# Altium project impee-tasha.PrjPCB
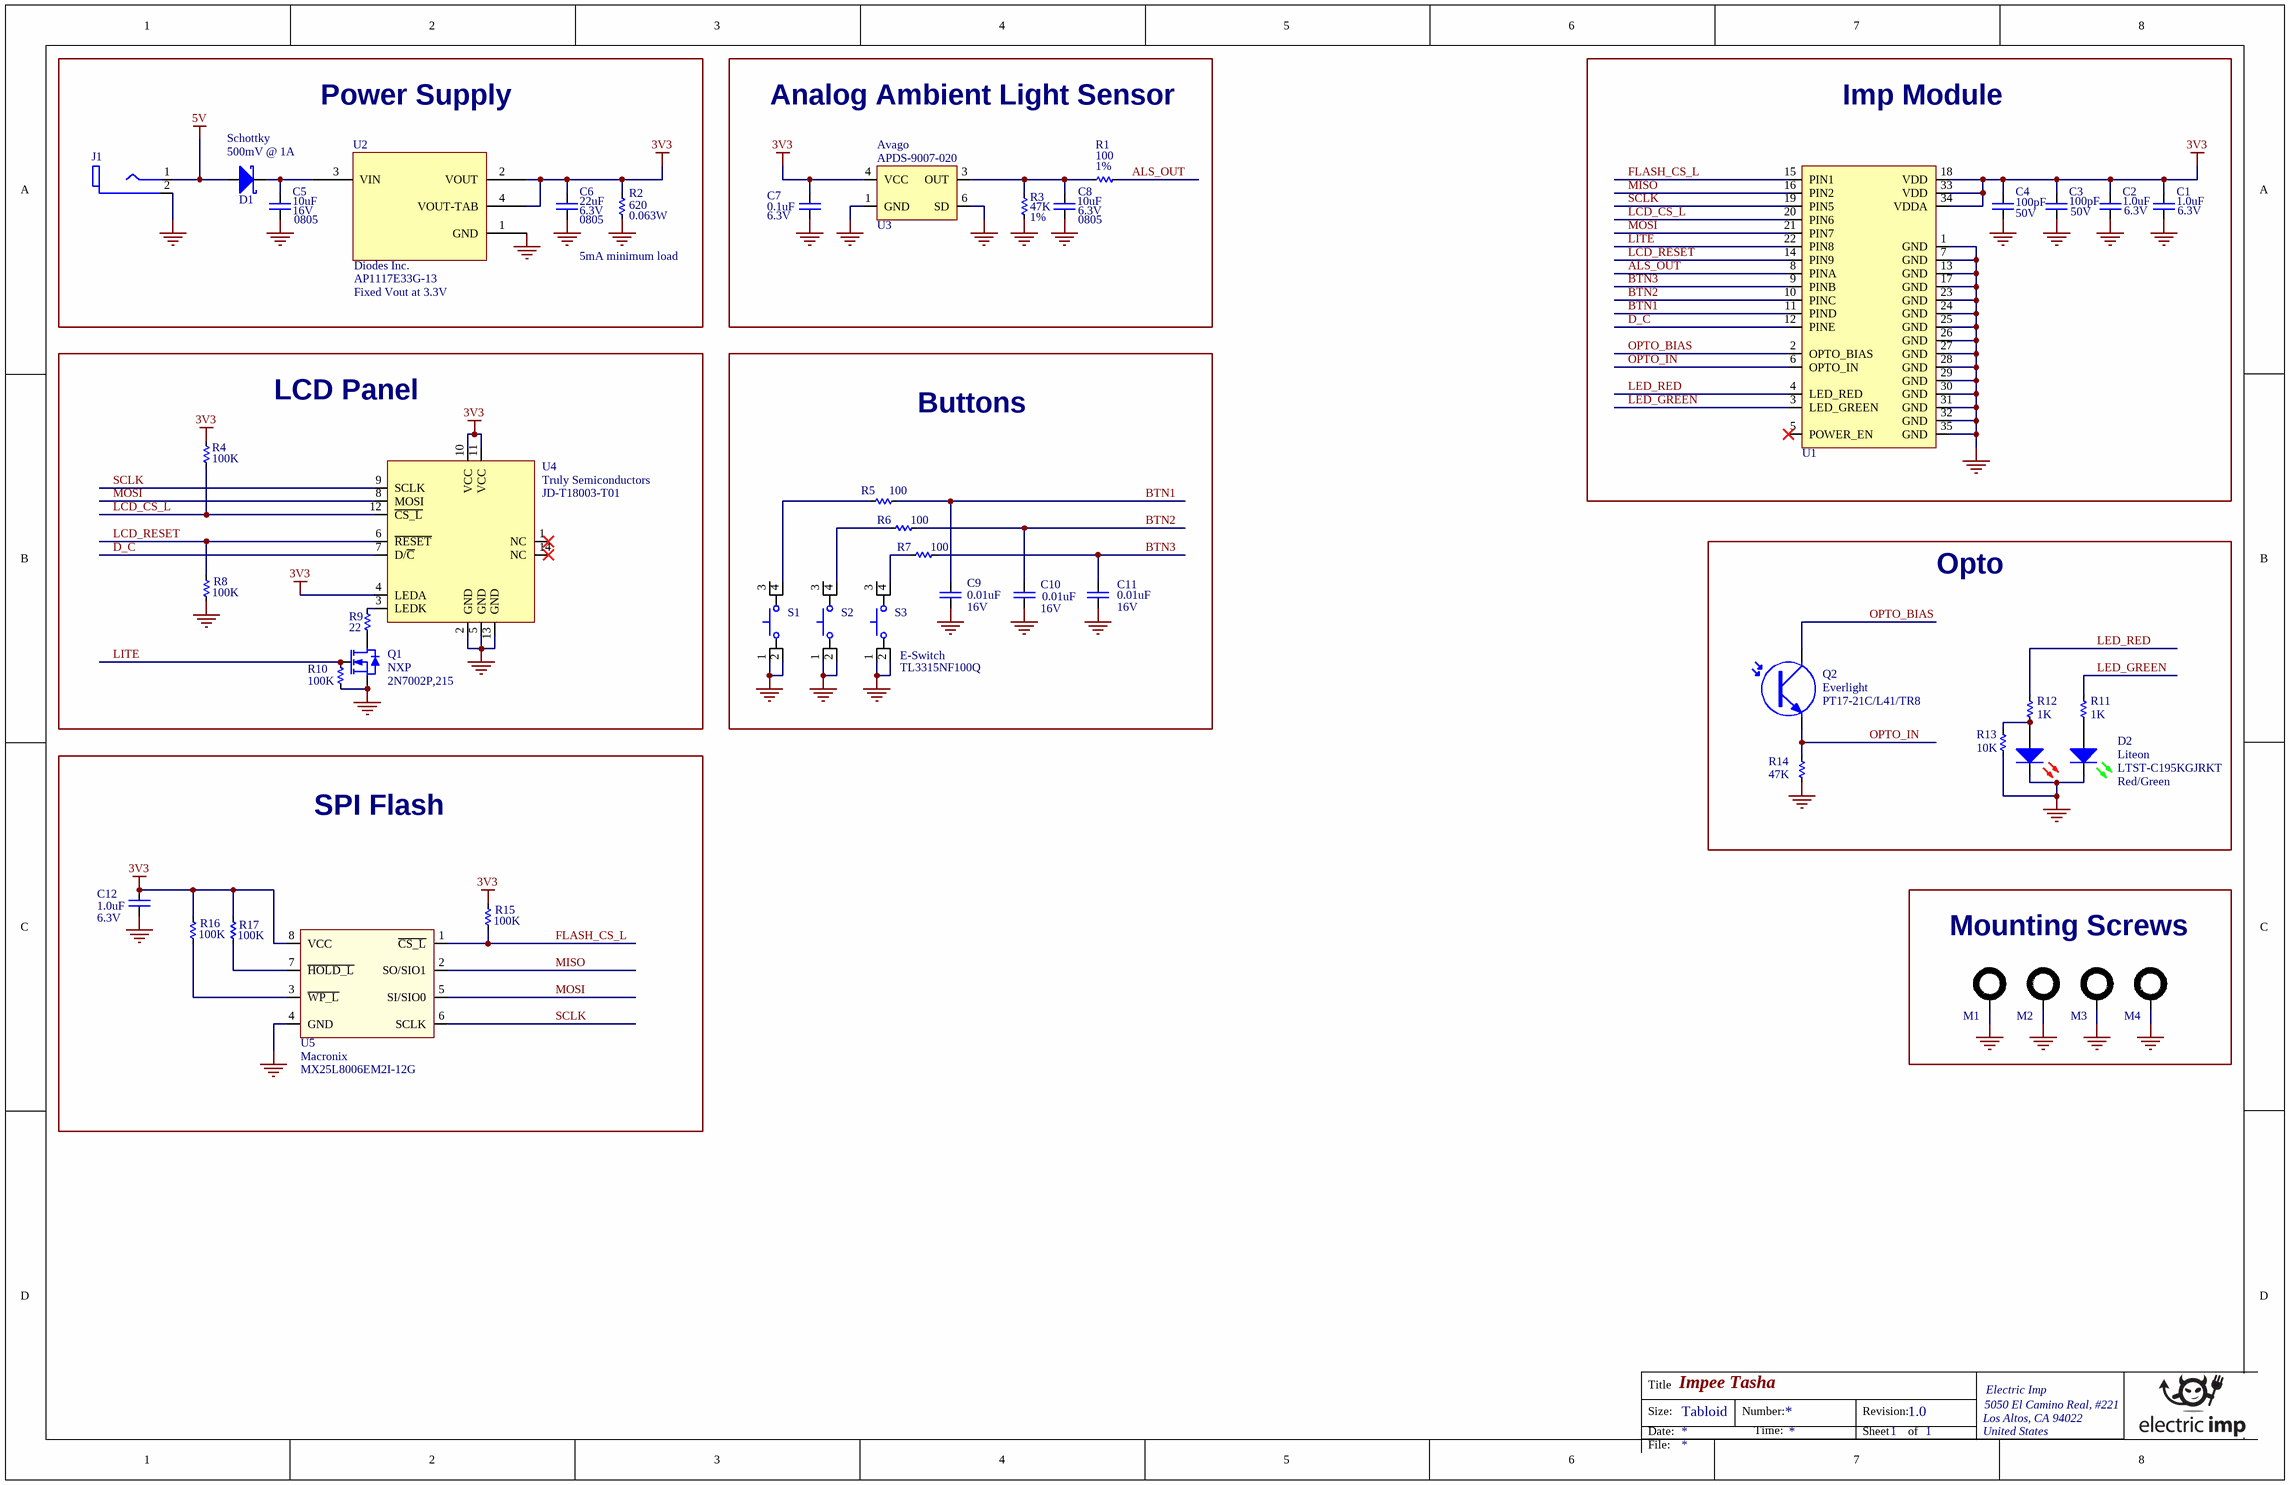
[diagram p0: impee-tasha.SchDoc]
1 sheet, 46 parts. Net scope: global (net labels, ports and power ports of the same name join across sheets).
Board file: impee-tasha.PcbDoc

## Sheet impee-tasha.SchDoc: Impee Tasha
size Tabloid; Address1: Electric Imp; Address2: 5050 El Camino Real, #221; Address3: Los Altos, CA 94022; Address4: United States; Revision: 1.0; SheetNumber: 1; SheetTotal: 1; PageSetup: Record=PageOptions¦CenterHorizontal=True¦CenterVertical=True¦PrintScale=0.98¦XCorrection=1.00¦YCorrection=1.00¦PrintKind=0¦BorderSize=5000000¦LeftOffset=0¦BottomOffset=0¦Orientation=2¦PaperLength=1000¦PaperWidth=1000¦Scale=100¦PaperSource=7¦PrintQuality=600¦MediaType=1¦DitherType=10¦PaperKind=Tabloid¦PrintScaleMode=1

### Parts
C1  value 1.0uF  Voltage: 6.3V  [CAPC1005X07N]  (hidden comment: Ceramic Capacitor)
C2  value 1.0uF  Voltage: 6.3V  [CAPC1005X07N]  (hidden comment: Ceramic Capacitor)
C3  value 100pF  Voltage: 50V  [CAPC1005X07N]  (hidden comment: Ceramic Capacitor)
C4  value 100pF  Voltage: 50V  [CAPC1005X07N]  (hidden comment: Ceramic Capacitor)
C5  value 10uF  Voltage: 16V  Package: 0805  [CAPC2012X14N]  (hidden comment: Ceramic Capacitor)
C6  value 22uF  Voltage: 6.3V  Package: 0805  [CAPC2012X14N]  (hidden comment: Ceramic Capacitor)
C7  value 0.1uF  Voltage: 6.3V  [CAPC1005X07N]  (hidden comment: Ceramic Capacitor)
C8  value 10uF  Voltage: 6.3V  Package: 0805  [CAPC2012X14N]  (hidden comment: Ceramic Capacitor)
C9  value 0.01uF  Voltage: 16V  [CAPC1005X07N]  (hidden comment: Ceramic Capacitor)
C10  value 0.01uF  Voltage: 16V  [CAPC1005X07N]  (hidden comment: Ceramic Capacitor)
C11  value 0.01uF  Voltage: 16V  [CAPC1005X07N]  (hidden comment: Ceramic Capacitor)
C12  value 1.0uF  Voltage: 6.3V  [CAPC1005X07N]  (hidden comment: Ceramic Capacitor)
D1  Voltage - Forward (Vf) (Max) @ If: 500mV @ 1A  [DO-214AC]  (hidden comment: Schottky Diode)
D2  Color: Red/Green  Manufacturer: Liteon  Manufacturer Part Number: LTST-C195KGJRKT  [LED1616X07N-REDGREEN]  (hidden comment: LED Red and Green)
J1  PWR2.1  [HDR1X2]  (value not drawn)
M1  Mounting Hole  [91772A074]  (value not drawn)  (no BOM)
M2  Mounting Hole  [91772A074]  (value not drawn)  (no BOM)
M3  Mounting Hole  [91772A074]  (value not drawn)  (no BOM)
M4  Mounting Hole  [91772A074]  (value not drawn)  (no BOM)
Q1  Manufacturer: NXP  Manufacturer Part Number: 2N7002P,215  [SOT95P300X130-3N]  (hidden comment: N-Channel MOSFET)
Q2  Manufacturer: Everlight  Manufacturer Part Number: PT17-21C/L41/TR8  [PHOTOTRANS2012X13]  (hidden comment: PHOTOTRANSISTOR)
R1  value 100  Tolerance: 1%  [RESC1005X04N]  (hidden comment: Resistor)
R2  value 620  Power: 0.063W  [RESC1005X04N]  (hidden comment: Resistor)
R3  value 47K  Tolerance: 1%  [RESC1005X04N]  (hidden comment: Resistor)
R4  value 100K  [RESC1005X04N]  (hidden comment: Resistor)
R5  value 100  [RESC1005X04N]  (hidden comment: Resistor)
R6  value 100  [RESC1005X04N]  (hidden comment: Resistor)
R7  value 100  [RESC1005X04N]  (hidden comment: Resistor)
R8  value 100K  [RESC1005X04N]  (hidden comment: Resistor)
R9  value 22  [RESC1005X04N]  (hidden comment: Resistor)
R10  value 100K  [RESC1005X04N]  (hidden comment: Resistor)
R11  value 1K  [RESC1005X04N]  (hidden comment: Resistor)
R12  value 1K  [RESC1005X04N]  (hidden comment: Resistor)
R13  value 10K  [RESC1005X04N]  (hidden comment: Resistor)
R14  value 47K  [RESC1005X04N]  (hidden comment: Resistor)
R15  value 100K  [RESC1005X04N]  (hidden comment: Resistor)
R16  value 100K  [RESC1005X04N]  (hidden comment: Resistor)
R17  value 100K  [RESC1005X04N]  (hidden comment: Resistor)
S1  Manufacturer: E-Switch  [TL3315NF100Q]  (hidden comment: Push Button)
S2  Push Button  [TL3315NF100Q]  (value not drawn)
S3  Push Button  [TL3315NF100Q]  (value not drawn)
U1  imp module  [IMP_MODULE]  (value not drawn)
U2  Manufacturer: Diodes Inc.  Manufacturer Part Number: AP1117E33G-13  Comment_1: Fixed Vout at 3.3V  [SOT230P700X180-4N]  (hidden comment: AP1117E33G)
U3  Manufacturer: Avago  Manufacturer Part Number: APDS-9007-020  [APDS-9007]  (hidden comment: APDS-9007)
U4  Manufacturer: Truly Semiconductors  [JD-T18003-T01]  (hidden comment: JD-T18003-T01)
U5  Manufacturer: Macronix  [SOIC127P790X216-8N]  (hidden comment: MX25L8006EM2I-12G)

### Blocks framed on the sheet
Power Supply: C5 C6 D1 J1 R2 U2
Analog Ambient Light Sensor: C7 C8 R1 R3 U3
Imp Module: C1-C4 U1
LCD Panel: Q1 R4 R8-R10 U4
Buttons: C9-C11 R5-R7 S1-S3
Opto: D2 Q2 R11-R14
SPI Flash: C12 R15-R17 U5
Mounting Screws: M1-M4

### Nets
3V3: C1.2 C2.2 C3.2 C4.2 C6.2 C7.2 C12.2 R2.2 R4.2 R15.2 R16.2 R17.2 U1.18(VDD) U1.33(VDD) U1.34(VDDA) U2.2(VOUT) U2.4(VOUT-TAB) U3.4(VCC) U4.4(LEDA) U4.10(VCC) U4.11(VCC) U5.8(VCC)
5V: D1.A J1.1
GND: C1.1 C2.1 C3.1 C4.1 C5.1 C6.1 C7.1 C8.1 C9.1 C10.1 C11.1 C12.1 D2.KG D2.KR J1.2 M1.1 M2.1 M3.1 M4.1 Q1.2(S) R2.1 R3.1 R8.1 R10.1 R13.2 R14.1 S1.1 S1.2 S2.1 S2.2 S3.1 S3.2 U1.1(GND) U1.7(GND) U1.13(GND) U1.17(GND) U1.23(GND) U1.24(GND) U1.25(GND) U1.26(GND) U1.27(GND) U1.28(GND) U1.29(GND) U1.30(GND) U1.31(GND) U1.32(GND) U1.35(GND) U2.1(GND) U3.1(GND) U3.6(SD) U4.2(GND) U4.5(GND) U4.13(GND) U5.4(GND)
ALS_OUT: R1.2 U1.8(PINA)
BTN1: C9.2 R5.1 U1.11(PIND)
BTN2: C10.2 R6.1 U1.10(PINC)
BTN3: C11.2 R7.1 U1.9(PINB)
D_C: U1.12(PINE) U4.7(D/~{C})
FLASH_CS_L: R15.1 U1.15(PIN1) U5.1(~{CS_L})
LCD_CS_L: R4.1 U1.20(PIN6) U4.12(~{CS_L})
LCD_RESET: R8.2 U1.14(PIN9) U4.6(~{RESET})
LED_GREEN: R11.2 U1.3(LED_GREEN)
LED_RED: R12.2 U1.4(LED_RED)
LITE: Q1.1(G) R10.2 U1.22(PIN8)
MISO: U1.16(PIN2) U5.2(SO/SIO1)
MOSI: U1.21(PIN7) U4.8(MOSI) U5.5(SI/SIO0)
OPTO_BIAS: Q2.C U1.2(OPTO_BIAS)
OPTO_IN: Q2.E R14.2 U1.6(OPTO_IN)
SCLK: U1.19(PIN5) U4.9(SCLK) U5.6(SCLK)
NetC5_2: C5.2 D1.K U2.3(VIN)
NetC8_2: C8.2 R1.1 R3.2 U3.3(OUT)
NetD2_AG: D2.AG R11.1
NetD2_AR: D2.AR R12.1 R13.1
NetQ1_3: Q1.3(D) R9.1
NetR5_2: R5.2 S1.4
NetR6_2: R6.2 S2.4
NetR7_2: R7.2 S3.4
NetR9_2: R9.2 U4.3(LEDK)
NetR16_1: R16.1 U5.3(~{WP_L})
NetR17_1: R17.1 U5.7(~{HOLD_L})

Not connected (* = marked no-connect by the designer): S1 3; S2 3; S3 3; U1 5(POWER_EN)*; U4 1(NC)* 14(NC)*

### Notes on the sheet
- 5mA minimum load

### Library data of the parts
C1 C2 C12 = CAPC00005: CAP,X5R,1.0uF,10%,6.3V, 0402,#; Manufacturer: Taiyo Yuden; Manufacturer Part Number: JMK105BJ105KV-F
C3 C4 = CAPC00043: CAP,C0G,100pF,5%,50V,0402; Manufacturer: Yageo; Manufacturer Part Number: CC0402JRNPO9BN101
C5 = CAPC00037: CAP,X5R,10uF,10%,16V,0805,#; Manufacturer: Taiyo Yuden; Manufacturer Part Number: EMK212BJ106KG-T
C6 = CAPC00039: CAP,X5R,22uF,10%,6.3V,0805,#; Manufacturer: TDK; Manufacturer Part Number: C2012X5R0J226K/1.25
C7 = CAPC00002: CAP,X5R,0.1uF,10%,6.3V, 0402,#; Manufacturer: TDK; Manufacturer Part Number: C1005X5R0J104K
C8 = CAPC00036: CAP,X5R,10uF,10%,6.3V,0805,#; Manufacturer: Yageo; Manufacturer Part Number: CC0805KKX5R5BB106
C9-C11 = CAPC00026: CAP,X7R,0.01uF,10%,16V,0402,#; Manufacturer: Yageo; Manufacturer Part Number: CC0402KRX7R7BB103
D1 = SCHOTTKY00001: DIODE, Schottky, 1A, 20V, DO-214AC; Manufacturer: Comchip Technology; Manufacturer Part Number: CDBA120-G
D2 = LED00012: LED, Red and Green, 2/2V, 631/571nm, 15/20mcd, SMT; Millicandela Rating (min): 15mcd, 20mcd; Voltage - Forward (Vf) Typ: 2V, 2V; Current - Test: 20mA; Wavelength - Dominant: 631nm, 571nm; Wavelength - Peak: 639nm, 574nm; Viewing Angle: 130°; Lens Type: Clear
J1 = CON00007: DC Power Jack, 2.1mm ID x 5.5mm OD, Panel mount, Front-side nut; Manufacturer: CUI; Manufacturer Part Number: PJ-005A
M1-M4 = MNT00001: #2-56 1/8" Phillips Machine Screw (Stainless Steel); Manufacturer: McMaster-Carr
Q1 = NFET00002: NFET, 60V, 360mA, SOT23; Drain to Source Voltage (Vdss): 50V; Rds On (Max) @ Id, Vgs: 1.6 Ohm @ 500mA, 10V; Vgs(th) (Max) @ Id: 2.4V @ 250µA; Power - Max: 350mW
Q2 = PHOTO00002: Phototrans, Clear, 940nm, 0.4V, 1mA, 0805
R1 R5-R7 = RES00024: RES,100 Ohm,1%,0.063W,0402,#; Manufacturer: Yageo; Manufacturer Part Number: RC0402FR-07100RL
R2 = RES00048: RES,620 Ohm,5%,0.063W,0402; Manufacturer: Yageo; Manufacturer Part Number: RC0402JR-07620RL
R3 = RES00042: RES,47K,1%,0.063W,0402; Manufacturer: Yageo; Manufacturer Part Number: RC0402FR-0747KL
R4 R8 R10 R15-R17 = RES00001: RES,100k,5%,0.063W,0402,#; Manufacturer: Stackpole; Manufacturer Part Number: RMCF0402JT100K
R9 = RES00060: RES,22,5%,0.063W,0402; Manufacturer: Yageo; Manufacturer Part Number: RC0402JR-0722RL
R11 R12 = RES00003: RES,1k,5%,0.063W,0402,#; Manufacturer: Yageo; Manufacturer Part Number: RC0402JR-071KL
R13 = RES00006: RES,10k,5%,0.063W,0402,#; Manufacturer: Stackpole; Manufacturer Part Number: RMCF0402JT10K0
R14 = RES00008: RES,47k,5%,0.063W,0402; Manufacturer: Yageo; Manufacturer Part Number: RC0402JR-0747KL
S1 = BTN00004: SPST-NO Snap Dome Switch 0.05A 15V
S2 S3 = BTN00004: SPST-NO Snap Dome Switch 0.05A 15V; Manufacturer: E-Switch
U1 = MOD00002: Module, Electric Imp Solder Down with Antenna; Manufacturer Part Number: IMP002
U2 = IC00033: IC, LDO, Fixed Output, 3.3V, 1A, SOT223
U3 = IC00030: IC, Sensor,Light, Logarithmic Output, SMT4
U4 = DISP00001: 1.8" Color TFT LCD, 128x160; Display Type: LCD - TFT; Backlight: LED - White, Dual; Interface: SPI + 2 I/O
U5 = IC00089: IC, SPI Flash, 8Mbit, 86MHz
